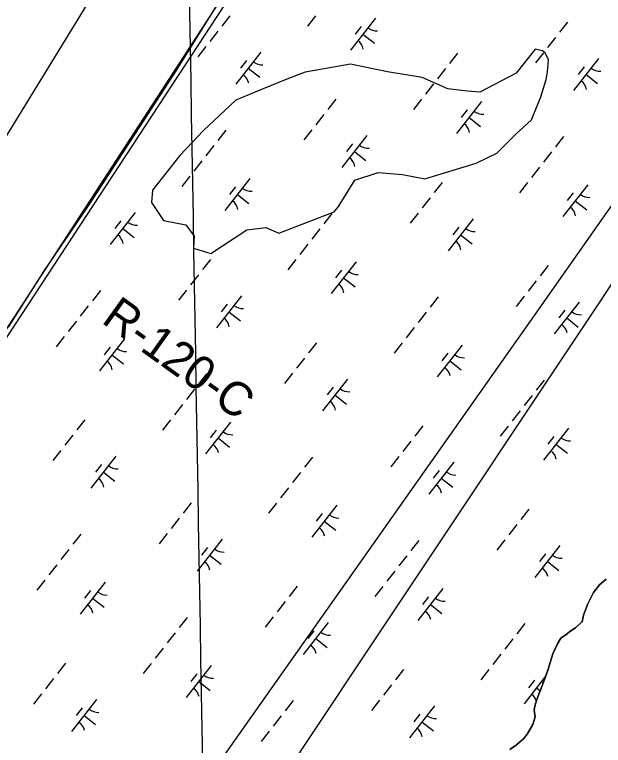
# Model space of a CAD drawing. Extents: x 3896831 to 3918110, y 171006 to 193349.
# Drawn here: x 3909451 to 3910177, y 179895 to 180795 of the extents above; entities that cross this region are included whole.
import ezdxf

# ---------------------------------------------------------------- set-up
doc = ezdxf.new("R2010")
doc.units = 0
for name, color, linetype in [('V-GRID-MAJR', 7, 'Continuous'), ('V-RIVR-EDGE', 7, 'Continuous'), ('V-RIVR-RANG-IDEN', 7, 'Continuous'), ('V-RRAP-FSHR', 7, 'Continuous'), ('V-TOPO-MINR', 7, 'Continuous'), ('V-TOPO-SHOR', 7, 'Continuous'), ('V-UTIL-LINE', 7, 'Continuous'), ('V-WETL-SWMP', 7, 'Continuous')]:
    doc.layers.add(name, color=color, linetype=linetype)

msp = doc.modelspace()

# ---------------------------------------------------------------- linework, layer by layer
at = {"layer": 'V-GRID-MAJR'}
msp.add_spline([(3909752.76, 175802.03), (3909660.52, 181175.42), (3909556.5, 187235.56), (3909500.71, 190486.24)], degree=3, dxfattribs=at)
at = {"layer": 'V-RIVR-EDGE'}
msp.add_lwpolyline([(3909879.56, 181084.54), (3909758.09, 180895.87), (3909427.42, 180388.01), (3909280.7, 180160.04), (3909036.93, 179790.99)], dxfattribs=at)
at = {"layer": 'V-RRAP-FSHR'}
msp.add_lwpolyline([(3910095.26, 181395.62), (3909257.26, 180118.06), (3908889.4, 179541.49), (3908614.71, 178888.41), (3907991.89, 177840.93), (3908307.01, 176956.59)], dxfattribs=at)
at = {"layer": 'V-TOPO-MINR'}
msp.add_lwpolyline([(3908993.78, 179917.96), (3909778.71, 181196.48), (3909782.38, 181202.03), (3909786.59, 181207.27), (3909882.73, 181311.02), (3909935.24, 181368.06), (3909987.51, 181425.34), (3910039.4, 181482.95), (3910091.03, 181540.8), (3910231.58, 181699.29), (3910240.41, 181709.39), (3910249.15, 181719.56), (3910257.75, 181729.84), (3910266.27, 181740.2), (3910415.71, 181924.58), (3910464.29, 181988.82), (3910509.83, 182055), (3910550.81, 182124.09), (3910588.76, 182195.13), (3910657.9, 182335.76), (3910918.8, 182961.55)], dxfattribs=at)
at = {"layer": 'V-TOPO-SHOR'}
msp.add_lwpolyline([(3909956.83, 180592.65), (3910020.2, 180612.28), (3910045.63, 180624.33), (3910069.64, 180648.16), (3910088.47, 180665.39), (3910099.99, 180693.68), (3910106.32, 180715.37), (3910108.2, 180724.56), (3910109.36, 180739.65), (3910105.34, 180748.13), (3910102.04, 180750.71), (3910092.85, 180752.59), (3910085.08, 180742.68), (3910069.55, 180722.87), (3910024.57, 180699.48), (3910009.49, 180700.64), (3909985.21, 180703.68), (3909953.62, 180717.78), (3909910.95, 180724.56), (3909864.99, 180733.93), (3909809.39, 180724.2), (3909786.54, 180715.45), (3909755.21, 180702.69), (3909723.88, 180689.93), (3909683.63, 180652.17), (3909654.45, 180621.74), (3909620.8, 180578.81), (3909619.64, 180563.73), (3909634.28, 180541.59), (3909661.86, 180535.97), (3909672.48, 180522.31), (3909671.32, 180507.23), (3909693.01, 180500.89), (3909737.27, 180530.17), (3909760.84, 180533.03), (3909776.63, 180525.97), (3909845.18, 180552.22), (3909850.36, 180558.82), (3909870.35, 180591.13), (3909899.09, 180600.59), (3909929.25, 180598.27)], close=True, dxfattribs=at)
msp.add_lwpolyline([(3910061.55, 179889.49), (3910069.82, 179895.45), (3910078.37, 179902.61), (3910082.9, 179908.52), (3910087.31, 179915.36), (3910090.22, 179920.24), (3910093.09, 179929.92), (3910091.79, 179937.95), (3910092.3, 179943.14), (3910094.88, 179951.36), (3910098.12, 179959.69), (3910101.93, 179969.35), (3910105.47, 179979.29), (3910109, 179988.55), (3910114.74, 180007.64), (3910120.34, 180019.93), (3910124.75, 180026.77), (3910131.11, 180031.18), (3910137.08, 180035.72), (3910142.49, 180039.34), (3910149.98, 180046.52), (3910150.79, 180046.9), (3910152.43, 180055.14), (3910157.66, 180068.9), (3910164.76, 180083.03), (3910172.43, 180092.47), (3910180.31, 180099.38)], dxfattribs=at)
at = {"layer": 'V-UTIL-LINE'}
for points in [[(3905549.44, 173652.6), (3906763.35, 174938.42), (3906949.45, 175132.98), (3906970.6, 175166.82), (3907325.89, 175860.48), (3907748.86, 176681.03), (3908142.21, 177273.18), (3908679.38, 178097.96), (3908869.71, 178381.35), (3908937.39, 178537.85), (3909170.02, 179117.31), (3909533.77, 179633.33), (3910092.08, 180424.27), (3910333.17, 180766.87), (3910760.37, 181291.35), (3910921.09, 181523.98), (3911225.63, 181951.18), (3911822.01, 182788.65), (3911961.59, 182987.44), (3912147.69, 183114.33), (3912722.93, 183841.83), (3913090.91, 184307.09), (3913848.01, 185258.76), (3914364.03, 185910.13)], [(3913133.2, 183520.38), (3913116.28, 183516.15), (3912989.39, 183516.15), (3912744.07, 183393.49), (3911902.37, 182441.81), (3910866.11, 181249.05), (3910603.87, 180952.98), (3910214.74, 180504.64), (3910138.61, 180390.43), (3909757.94, 179819.43), (3909457.64, 179366.86), (3909009.29, 178685.89), (3908785.12, 178351.74), (3908150.67, 177400.07), (3907770.01, 176816.38), (3907693.87, 176706.41), (3907647.35, 176630.28), (3907300.51, 175936.61), (3907025.59, 175369.84), (3906945.22, 175204.88), (3906416.52, 174650.8), (3905507.14, 173682.21)]]:
    msp.add_lwpolyline(points, dxfattribs=at)
at = {"layer": 'V-WETL-SWMP'}
for p, q in [((3909651.13, 180727.13), (3909720.16, 180838.26)), ((3909716.31, 180793.65), (3909706.44, 180781.06)), ((3909821.77, 180793.52), (3909811.9, 180780.93)), ((3909895.91, 180790.79), (3909865.07, 180751.43)), ((3910132.95, 180785.95), (3910123.08, 180773.36)), ((3909701.51, 180774.76), (3909691.64, 180762.17)), ((3909878.12, 180780.59), (3909870.71, 180771.15)), ((3909880.49, 180771.11), (3909894.65, 180760.01)), ((3910118.15, 180767.06), (3910108.28, 180754.47)), ((3909686.7, 180755.87), (3909676.83, 180743.28)), ((3909754.52, 180748.84), (3909723.67, 180709.48)), ((3909997.11, 180747.58), (3909987.24, 180734.99)), ((3910103.34, 180748.17), (3910093.48, 180735.58)), ((3910103.34, 180748.17), (3910093.48, 180735.58)), ((3909736.73, 180738.64), (3909729.32, 180729.2)), ((3910171.16, 180741.14), (3910140.32, 180701.78)), ((3910153.37, 180730.94), (3910145.97, 180721.5)), ((3909542.79, 180560.93), (3909651.13, 180727.13)), ((3909739.1, 180729.16), (3909753.26, 180718.06)), ((3909982.3, 180728.69), (3909972.43, 180716.1)), ((3910155.74, 180721.46), (3910169.91, 180710.36)), ((3909967.5, 180709.8), (3909957.63, 180697.21)), ((3909967.5, 180709.8), (3909957.63, 180697.21)), ((3909847.23, 180691.04), (3909837.36, 180678.45)), ((3909847.23, 180691.04), (3909837.36, 180678.45)), ((3909952.69, 180690.91), (3909942.82, 180678.32)), ((3909952.69, 180690.91), (3909942.82, 180678.32)), ((3910026.83, 180688.18), (3909995.98, 180648.82)), ((3910026.83, 180688.18), (3909995.98, 180648.82)), ((3910009.03, 180677.98), (3910001.63, 180668.54)), ((3910009.03, 180677.98), (3910001.63, 180668.54)), ((3909832.43, 180672.15), (3909822.56, 180659.56)), ((3909832.43, 180672.15), (3909822.56, 180659.56)), ((3910011.41, 180668.5), (3910025.57, 180657.4)), ((3910011.41, 180668.5), (3910025.57, 180657.4)), ((3909711.38, 180652.67), (3909701.51, 180640.08)), ((3909711.38, 180652.67), (3909701.51, 180640.08)), ((3909817.62, 180653.26), (3909807.75, 180640.67)), ((3909817.62, 180653.26), (3909807.75, 180640.67)), ((3909885.44, 180646.23), (3909854.59, 180606.87)), ((3909885.44, 180646.23), (3909854.59, 180606.87)), ((3910128.03, 180644.97), (3910118.16, 180632.38)), ((3909696.58, 180633.78), (3909686.71, 180621.19)), ((3909696.58, 180633.78), (3909686.71, 180621.19)), ((3909867.64, 180636.03), (3909860.24, 180626.59)), ((3909867.64, 180636.03), (3909860.24, 180626.59)), ((3909870.01, 180626.55), (3909884.18, 180615.45)), ((3909870.01, 180626.55), (3909884.18, 180615.45)), ((3910113.22, 180626.08), (3910103.35, 180613.49)), ((3909681.77, 180614.89), (3909671.9, 180602.3)), ((3909681.77, 180614.89), (3909671.9, 180602.3)), ((3910098.42, 180607.19), (3910088.55, 180594.6)), ((3909666.97, 180596), (3909657.1, 180583.41)), ((3909666.97, 180596), (3909657.1, 180583.41)), ((3909741.1, 180593.27), (3909710.26, 180553.92)), ((3909741.1, 180593.27), (3909710.26, 180553.92)), ((3909978.15, 180588.43), (3909968.28, 180575.84)), ((3910083.61, 180588.3), (3910073.74, 180575.71)), ((3910157.75, 180585.57), (3910126.9, 180546.22)), ((3909723.31, 180583.07), (3909715.91, 180573.63)), ((3909723.31, 180583.07), (3909715.91, 180573.63)), ((3909725.68, 180573.59), (3909739.85, 180562.49)), ((3909725.68, 180573.59), (3909739.85, 180562.49)), ((3909963.34, 180569.55), (3909953.47, 180556.95)), ((3910139.95, 180575.37), (3910132.55, 180565.93)), ((3909486.81, 180478.48), (3909542.79, 180560.93)), ((3910142.32, 180565.89), (3910156.49, 180554.79)), ((3909599.71, 180551.32), (3909568.87, 180511.97)), ((3909842.3, 180550.06), (3909832.43, 180537.47)), ((3909948.54, 180550.66), (3909938.67, 180538.06)), ((3909581.92, 180541.12), (3909574.52, 180531.68)), ((3910016.36, 180543.62), (3909985.51, 180504.27)), ((3909584.29, 180531.64), (3909598.46, 180520.54)), ((3909998.56, 180533.42), (3909991.16, 180523.98)), ((3909827.5, 180531.17), (3909817.63, 180518.58)), ((3910000.93, 180523.94), (3910015.1, 180512.84)), ((3909812.69, 180512.28), (3909802.82, 180499.69)), ((3909692.42, 180493.53), (3909682.55, 180480.93)), ((3909797.89, 180493.4), (3909788.02, 180480.8)), ((3909872.02, 180490.66), (3909841.18, 180451.31)), ((3909458.41, 180433.77), (3909486.81, 180478.48)), ((3909854.23, 180480.47), (3909846.83, 180471.02)), ((3910109.07, 180485.83), (3910099.2, 180473.23)), ((3909677.62, 180474.64), (3909667.75, 180462.04)), ((3909856.6, 180470.98), (3909870.77, 180459.88)), ((3910094.26, 180466.94), (3910084.39, 180454.34)), ((3909556.58, 180455.16), (3909546.71, 180442.56)), ((3909662.81, 180455.75), (3909652.94, 180443.15)), ((3909730.63, 180448.71), (3909699.79, 180409.36)), ((3909973.22, 180447.46), (3909963.35, 180434.86)), ((3910079.46, 180448.05), (3910069.59, 180435.45)), ((3909443.47, 180410.03), (3909458.41, 180433.77)), ((3909541.77, 180436.27), (3909531.9, 180423.67)), ((3909712.84, 180438.52), (3909705.44, 180429.07)), ((3910147.27, 180441.01), (3910116.43, 180401.66)), ((3909715.21, 180429.03), (3909729.38, 180417.93)), ((3909958.42, 180428.57), (3909948.55, 180415.97)), ((3910129.48, 180430.82), (3910122.08, 180421.37)), ((3909526.97, 180417.38), (3909517.1, 180404.78)), ((3910131.85, 180421.33), (3910146.02, 180410.23)), ((3909943.61, 180409.68), (3909933.74, 180397.08)), ((3909512.16, 180398.49), (3909502.29, 180385.89)), ((3909586.3, 180395.75), (3909555.45, 180356.4)), ((3909823.34, 180390.92), (3909813.47, 180378.32)), ((3909928.81, 180390.79), (3909918.94, 180378.19)), ((3910002.94, 180388.05), (3909972.1, 180348.7)), ((3909568.5, 180385.56), (3909561.1, 180376.11)), ((3909570.88, 180376.07), (3909585.04, 180364.97)), ((3909808.54, 180372.03), (3909798.67, 180359.43)), ((3909985.15, 180377.86), (3909977.74, 180368.41)), ((3909987.52, 180368.37), (3910001.69, 180357.27)), ((3909687.5, 180352.55), (3909677.63, 180339.95)), ((3909793.73, 180353.14), (3909783.86, 180340.55)), ((3909861.55, 180346.1), (3909830.71, 180306.75)), ((3910104.14, 180344.85), (3910094.27, 180332.25)), ((3909672.69, 180333.66), (3909662.82, 180321.06)), ((3909843.76, 180335.91), (3909836.35, 180326.46)), ((3909846.13, 180326.43), (3909860.29, 180315.32)), ((3910089.33, 180325.96), (3910079.46, 180313.36)), ((3909657.89, 180314.77), (3909648.02, 180302.17)), ((3910074.53, 180307.07), (3910064.66, 180294.47)), ((3909537.62, 180296.01), (3909527.75, 180283.42)), ((3909643.08, 180295.88), (3909633.21, 180283.28)), ((3909717.22, 180293.14), (3909686.37, 180253.79)), ((3909954.26, 180288.31), (3909944.39, 180275.72)), ((3909699.42, 180282.95), (3909692.02, 180273.5)), ((3910059.72, 180288.18), (3910049.85, 180275.59)), ((3910133.86, 180285.44), (3910103.01, 180246.09)), ((3909522.81, 180277.12), (3909512.94, 180264.53)), ((3909701.79, 180273.47), (3909715.96, 180262.36)), ((3910116.07, 180275.25), (3910108.66, 180265.8)), ((3909939.46, 180269.42), (3909929.59, 180256.83)), ((3910118.44, 180265.77), (3910132.6, 180254.66)), ((3909508.01, 180258.23), (3909498.14, 180245.64)), ((3909575.82, 180251.19), (3909544.98, 180211.84)), ((3909818.41, 180249.94), (3909808.54, 180237.35)), ((3909924.65, 180250.53), (3909914.78, 180237.94)), ((3909992.47, 180243.49), (3909961.62, 180204.14)), ((3909558.03, 180241), (3909550.63, 180231.55)), ((3909560.4, 180231.52), (3909574.57, 180220.41)), ((3909803.61, 180231.05), (3909793.74, 180218.46)), ((3909974.67, 180233.3), (3909967.27, 180223.85)), ((3909977.05, 180223.82), (3909991.21, 180212.71)), ((3909788.8, 180212.16), (3909778.93, 180199.57)), ((3909668.54, 180193.4), (3909658.67, 180180.81)), ((3909774, 180193.27), (3909764.13, 180180.68)), ((3909848.13, 180190.53), (3909817.29, 180151.18)), ((3909830.34, 180180.34), (3909822.94, 180170.89)), ((3910085.18, 180185.7), (3910075.31, 180173.11)), ((3909653.73, 180174.51), (3909643.86, 180161.92)), ((3909832.71, 180170.86), (3909846.88, 180159.75)), ((3910070.37, 180166.81), (3910060.51, 180154.22)), ((3909532.69, 180155.03), (3909522.82, 180142.44)), ((3909638.93, 180155.62), (3909629.06, 180143.03)), ((3909706.74, 180148.59), (3909675.9, 180109.23)), ((3909949.33, 180147.33), (3909939.46, 180134.74)), ((3910055.57, 180147.92), (3910045.7, 180135.33)), ((3909517.89, 180136.14), (3909508.02, 180123.55)), ((3909688.95, 180138.39), (3909681.55, 180128.95)), ((3910123.39, 180140.89), (3910092.54, 180101.53)), ((3909691.32, 180128.91), (3909705.49, 180117.8)), ((3909934.53, 180128.44), (3909924.66, 180115.85)), ((3910105.59, 180130.69), (3910098.19, 180121.25)), ((3909503.08, 180117.25), (3909493.21, 180104.66)), ((3910107.96, 180121.21), (3910122.13, 180110.11)), ((3909919.72, 180109.55), (3909909.85, 180096.96)), ((3910180.31, 180099.38), (3910172.43, 180092.47)), ((3909488.28, 180098.36), (3909478.41, 180085.77)), ((3909562.41, 180095.63), (3909531.57, 180056.27)), ((3909799.46, 180090.79), (3909789.59, 180078.2)), ((3909904.92, 180090.66), (3909895.05, 180078.07)), ((3910172.43, 180092.47), (3910164.76, 180083.03)), ((3909544.62, 180085.43), (3909537.21, 180075.99)), ((3909979.05, 180087.93), (3909948.21, 180048.57)), ((3910164.76, 180083.03), (3910157.66, 180068.9)), ((3909546.99, 180075.95), (3909561.15, 180064.85)), ((3909961.26, 180077.73), (3909953.86, 180068.29)), ((3909784.65, 180071.9), (3909774.78, 180059.31)), ((3909963.63, 180068.25), (3909977.8, 180057.15)), ((3910157.66, 180068.9), (3910152.43, 180055.14)), ((3910152.43, 180055.14), (3910150.79, 180046.9)), ((3909663.61, 180052.42), (3909653.74, 180039.83)), ((3909769.85, 180053.01), (3909759.98, 180040.42)), ((3909837.66, 180045.98), (3909806.82, 180006.62)), ((3910149.98, 180046.52), (3910142.49, 180039.34)), ((3910150.79, 180046.9), (3910149.98, 180046.52)), ((3910080.25, 180044.72), (3910070.38, 180032.13)), ((3910142.49, 180039.34), (3910137.08, 180035.72)), ((3909648.8, 180033.53), (3909638.93, 180020.94)), ((3909819.87, 180035.78), (3909812.47, 180026.34)), ((3910131.11, 180031.18), (3910124.75, 180026.77)), ((3910137.08, 180035.72), (3910131.11, 180031.18)), ((3909822.24, 180026.3), (3909836.41, 180015.2)), ((3910065.45, 180025.83), (3910055.58, 180013.24)), ((3910120.34, 180019.93), (3910114.74, 180007.64)), ((3910124.75, 180026.77), (3910120.34, 180019.93)), ((3909634, 180014.64), (3909624.13, 180002.05)), ((3910050.64, 180006.94), (3910040.77, 179994.35)), ((3910114.74, 180007.64), (3910109, 179988.55)), ((3909513.73, 179995.88), (3909503.86, 179983.29)), ((3909619.19, 179995.75), (3909609.32, 179983.16)), ((3909693.33, 179993.02), (3909662.48, 179953.66)), ((3909675.53, 179982.82), (3909668.13, 179973.38)), ((3909930.37, 179988.18), (3909920.5, 179975.59)), ((3910035.84, 179988.05), (3910025.97, 179975.46)), ((3910109, 179988.55), (3910105.47, 179979.29)), ((3909498.93, 179976.99), (3909489.06, 179964.4)), ((3909677.91, 179973.34), (3909692.07, 179962.24)), ((3910105.69, 179979.85), (3910079.13, 179945.96)), ((3910092.18, 179975.12), (3910084.78, 179965.68)), ((3910105.47, 179979.29), (3910101.93, 179969.35)), ((3909915.57, 179969.29), (3909905.7, 179956.7)), ((3910094.55, 179965.64), (3910099.07, 179962.1)), ((3910101.93, 179969.35), (3910098.12, 179959.7)), ((3909484.12, 179958.1), (3909474.25, 179945.51)), ((3910098.12, 179959.7), (3910094.88, 179951.36)), ((3909551.94, 179951.07), (3909521.09, 179911.71)), ((3909794.53, 179949.81), (3909784.66, 179937.22)), ((3909900.76, 179950.4), (3909890.89, 179937.81)), ((3910094.88, 179951.36), (3910092.3, 179943.14)), ((3909534.14, 179940.87), (3909526.74, 179931.43)), ((3909968.58, 179943.37), (3909937.74, 179904.01)), ((3910092.3, 179943.14), (3910091.79, 179937.95)), ((3910091.79, 179937.95), (3910093.09, 179929.92)), ((3909536.52, 179931.39), (3909550.68, 179920.29)), ((3909779.72, 179930.92), (3909769.85, 179918.33)), ((3909950.79, 179933.17), (3909943.38, 179923.73)), ((3910093.09, 179929.92), (3910090.22, 179920.24)), ((3909953.16, 179923.69), (3909967.33, 179912.59)), ((3910090.22, 179920.24), (3910087.31, 179915.36)), ((3909764.92, 179912.03), (3909755.05, 179899.44)), ((3910087.31, 179915.36), (3910082.9, 179908.52)), ((3910078.37, 179902.61), (3910069.82, 179895.45)), ((3910082.9, 179908.52), (3910078.37, 179902.61)), ((3910069.82, 179895.45), (3910061.55, 179889.49))]:
    msp.add_line(p, q, dxfattribs=at)
msp.add_lwpolyline([(3909956.83, 180592.65), (3910020.2, 180612.28), (3910045.63, 180624.33), (3910069.64, 180648.16), (3910088.47, 180665.39), (3910099.99, 180693.68), (3910106.32, 180715.37), (3910108.2, 180724.56), (3910109.36, 180739.65), (3910105.34, 180748.13), (3910102.04, 180750.71), (3910092.85, 180752.59), (3910085.08, 180742.68), (3910069.55, 180722.87), (3910024.57, 180699.48), (3910009.49, 180700.64), (3909985.21, 180703.68), (3909953.62, 180717.78), (3909910.95, 180724.56), (3909864.99, 180733.93), (3909809.39, 180724.2), (3909786.54, 180715.45), (3909755.21, 180702.69), (3909723.88, 180689.93), (3909683.63, 180652.17), (3909654.45, 180621.74), (3909620.8, 180578.81), (3909619.64, 180563.73), (3909634.28, 180541.59), (3909661.86, 180535.97), (3909672.48, 180522.31), (3909671.32, 180507.23), (3909693.01, 180500.89), (3909737.27, 180530.17), (3909760.84, 180533.03), (3909776.63, 180525.97), (3909845.18, 180552.22), (3909850.36, 180558.82), (3909870.35, 180591.13), (3909899.09, 180600.59), (3909929.25, 180598.27)], close=True, dxfattribs=at)
for centre, start, end in [((3909897.71, 180792.7), 231.14028, 272.68394), ((3909863.63, 180749.22), 11.14028, 52.68394), ((3909756.32, 180750.75), 231.14028, 272.68394), ((3909722.24, 180707.27), 11.14028, 52.68394), ((3910172.97, 180743.05), 231.14028, 272.68394), ((3910138.89, 180699.57), 11.14028, 52.68394), ((3910028.63, 180690.09), 231.14028, 272.68394), ((3910028.63, 180690.09), 231.14028, 272.68394), ((3909994.55, 180646.61), 11.14028, 52.68394), ((3909994.55, 180646.61), 11.14028, 52.68394), ((3909887.24, 180648.14), 231.14028, 272.68394), ((3909887.24, 180648.14), 231.14028, 272.68394), ((3909853.16, 180604.67), 11.14028, 52.68394), ((3909853.16, 180604.67), 11.14028, 52.68394), ((3909742.91, 180595.19), 231.14028, 272.68394), ((3909742.91, 180595.19), 231.14028, 272.68394), ((3910159.55, 180587.49), 231.14028, 272.68394), ((3909708.83, 180551.71), 11.14028, 52.68394), ((3909708.83, 180551.71), 11.14028, 52.68394), ((3910125.47, 180544.01), 11.14028, 52.68394), ((3909601.52, 180553.24), 231.14028, 272.68394), ((3910018.16, 180545.54), 231.14028, 272.68394), ((3909567.44, 180509.76), 11.14028, 52.68394), ((3909984.08, 180502.06), 11.14028, 52.68394), ((3909873.83, 180492.58), 231.14028, 272.68394), ((3909839.75, 180449.1), 11.14028, 52.68394), ((3909732.43, 180450.63), 231.14028, 272.68394), ((3910149.08, 180442.93), 231.14028, 272.68394), ((3909698.36, 180407.15), 11.14028, 52.68394), ((3910115, 180399.45), 11.14028, 52.68394), ((3909588.1, 180397.67), 231.14028, 272.68394), ((3910004.74, 180389.97), 231.14028, 272.68394), ((3909554.02, 180354.19), 11.14028, 52.68394), ((3909970.67, 180346.49), 11.14028, 52.68394), ((3909863.35, 180348.02), 231.14028, 272.68394), ((3909829.28, 180304.54), 11.14028, 52.68394), ((3909719.02, 180295.06), 231.14028, 272.68394), ((3910135.66, 180287.36), 231.14028, 272.68394), ((3909684.94, 180251.58), 11.14028, 52.68394), ((3910101.58, 180243.88), 11.14028, 52.68394), ((3909577.63, 180253.11), 231.14028, 272.68394), ((3909994.27, 180245.41), 231.14028, 272.68394), ((3909543.55, 180209.63), 11.14028, 52.68394), ((3909960.19, 180201.93), 11.14028, 52.68394), ((3909849.94, 180192.45), 231.14028, 272.68394), ((3909815.86, 180148.97), 11.14028, 52.68394), ((3909708.55, 180150.5), 231.14028, 272.68394), ((3910125.19, 180142.8), 231.14028, 272.68394), ((3909674.47, 180107.02), 11.14028, 52.68394), ((3910091.11, 180099.32), 11.14028, 52.68394), ((3909564.21, 180097.54), 231.14028, 272.68394), ((3909980.86, 180089.84), 231.14028, 272.68394), ((3909530.14, 180054.06), 11.14028, 52.68394), ((3909946.78, 180046.36), 11.14028, 52.68394), ((3909839.47, 180047.89), 231.14028, 272.68394), ((3909805.39, 180004.41), 11.14028, 52.68394), ((3909695.13, 179994.93), 231.14028, 272.68394), ((3910111.77, 179987.23), 231.14028, 239.68017), ((3909661.05, 179951.45), 11.14028, 52.68394), ((3910077.7, 179943.75), 19.35932, 52.68394), ((3909553.74, 179952.98), 231.14028, 272.68394), ((3909970.38, 179945.28), 231.14028, 272.68394), ((3909519.66, 179909.51), 11.14028, 52.68394), ((3909936.31, 179901.81), 11.14028, 52.68394)]:
    msp.add_arc(centre, 17.62, start, end, dxfattribs=at)

# ---------------------------------------------------------------- texts
at = {"layer": 'V-RIVR-RANG-IDEN'}
msp.add_text('R-120-C', height=41.5, rotation=324.36212, dxfattribs=at).set_placement((3909556.54, 180416.38))

doc.saveas('drawing.dxf')
